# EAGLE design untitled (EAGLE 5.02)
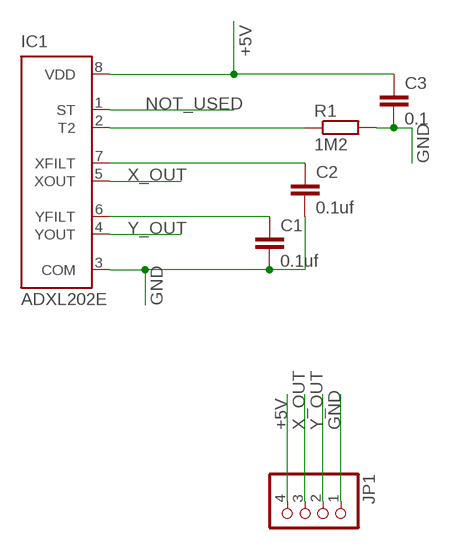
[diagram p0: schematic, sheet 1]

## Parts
C1  0.1uf  C-EU025-025X050  [C025-025X050]
C2  0.1uf  C-EU025-025X050  [C025-025X050]
C3  0.1  C-EU025-025X050  [C025-025X050]
IC1  ADXL202E  [LCC8]
JP1  PINHD-1X4  [1X04]
R1  1M2  R-EU_0204/2V  [0204V]

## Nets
+5V: C3.1 IC1.8(VDD) JP1.4
GND: C1.2 C2.2 C3.2 IC1.3(COM) JP1.1 R1.2
N$1: IC1.2(T2) R1.1
N$2: C1.1 IC1.6(YFILT)
N$3: C2.1 IC1.7(XFILT)
NOT_USED: IC1.1(ST)
X_OUT: IC1.5(XOUT) JP1.3
Y_OUT: IC1.4(YOUT) JP1.2

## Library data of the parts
C1-C3 = rcl:C-EU: CAPACITOR, European symbol
IC1 = analog-devices:ADXL202E: Low-Cost +-2 g Dual-Axis Accelerometer with Duty Cycle Output Source: www.analog.com/UploadedFiles/Data_Sheets/53728567227477ADXL202E_a.pdf
JP1 = pinhead:PINHD-1X4: PIN HEADER
R1 = rcl:R-EU_: RESISTOR, European symbol

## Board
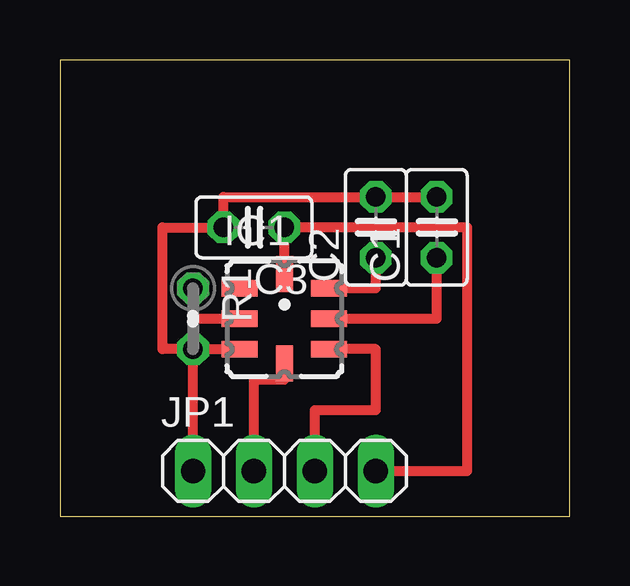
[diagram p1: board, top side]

Size 21.26 x 19.04 mm. Coordinates in mm from the lower left corner, seen from the top.
Outline: 0,0 21.26,0 21.26,19.04 0,19.04 0,0
Copper layers (1*16): Top 0.035mm / dielectric 1.5mm / Bottom 0.035mm
Design rules "default": minimum track width 10mil, minimum drill 24mil, track to track 8mil, track to pad 8mil, pad to pad 8mil, via to via 8mil, smd to smd 8mil, copper to edge 40mil, drill to drill 8mil, minimum pad ring 10mil, minimum via ring 8mil, stop-mask expansion 4mil, vias tented up to drill 0mil, thermal gap 10mil

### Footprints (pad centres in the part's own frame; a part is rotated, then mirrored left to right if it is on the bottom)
C025-025X050 = drill 0.813 octagon: 1 -1.27,0; 2 1.27,0
LCC8 = smd 1.5 x 0.7: 1 -1.867,1.27; 2 -1.867,0; 3 -1.867,-1.27; 5 1.867,-1.27; 6 1.867,0; 7 1.867,1.27 | smd 0.7 x 1.5: 4 0,-1.867; 8 0,1.867
1X04 = drill 1.016 long: 1 -3.81,0; 2 -1.27,0; 3 1.27,0; 4 3.81,0
0204V = drill 0.813 octagon: 1 -1.27,0; 2 1.27,0

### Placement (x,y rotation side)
C1  [C025-025X050]  15.71,12.06 90 top
C2  [C025-025X050]  13.17,12.06 90 top
C3  [C025-025X050]  8.09,12.06 180 top
IC1  9.36,8.25 0 top
JP1  9.36,1.9 0 top
R1  5.55,8.25 270 top

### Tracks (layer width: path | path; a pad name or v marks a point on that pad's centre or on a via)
+5V
  Top 0.406: JP1.4 16.98,1.9 16.98,12.06 C3.1 IC1.8
GND
  Top 0.406: R1.2 4.28,6.98 4.28,12.06 C3.2 6.82,13.33 C2.2 C1.2 | R1.2 IC1.3 | JP1.1 R1.2
N$1
  Top 0.406: IC1.2 5.55,8.25 R1.1
N$2
  Top 0.406: IC1.6 15.71,8.25 C1.1
N$3
  Top 0.406: IC1.7 13.17,9.52 C2.1
X_OUT
  Top 0.406: IC1.5 13.17,6.98 13.17,4.44 10.63,4.44 JP1.3
Y_OUT
  Top 0.406: JP1.2 8.09,5.71 9.36,5.71 IC1.4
